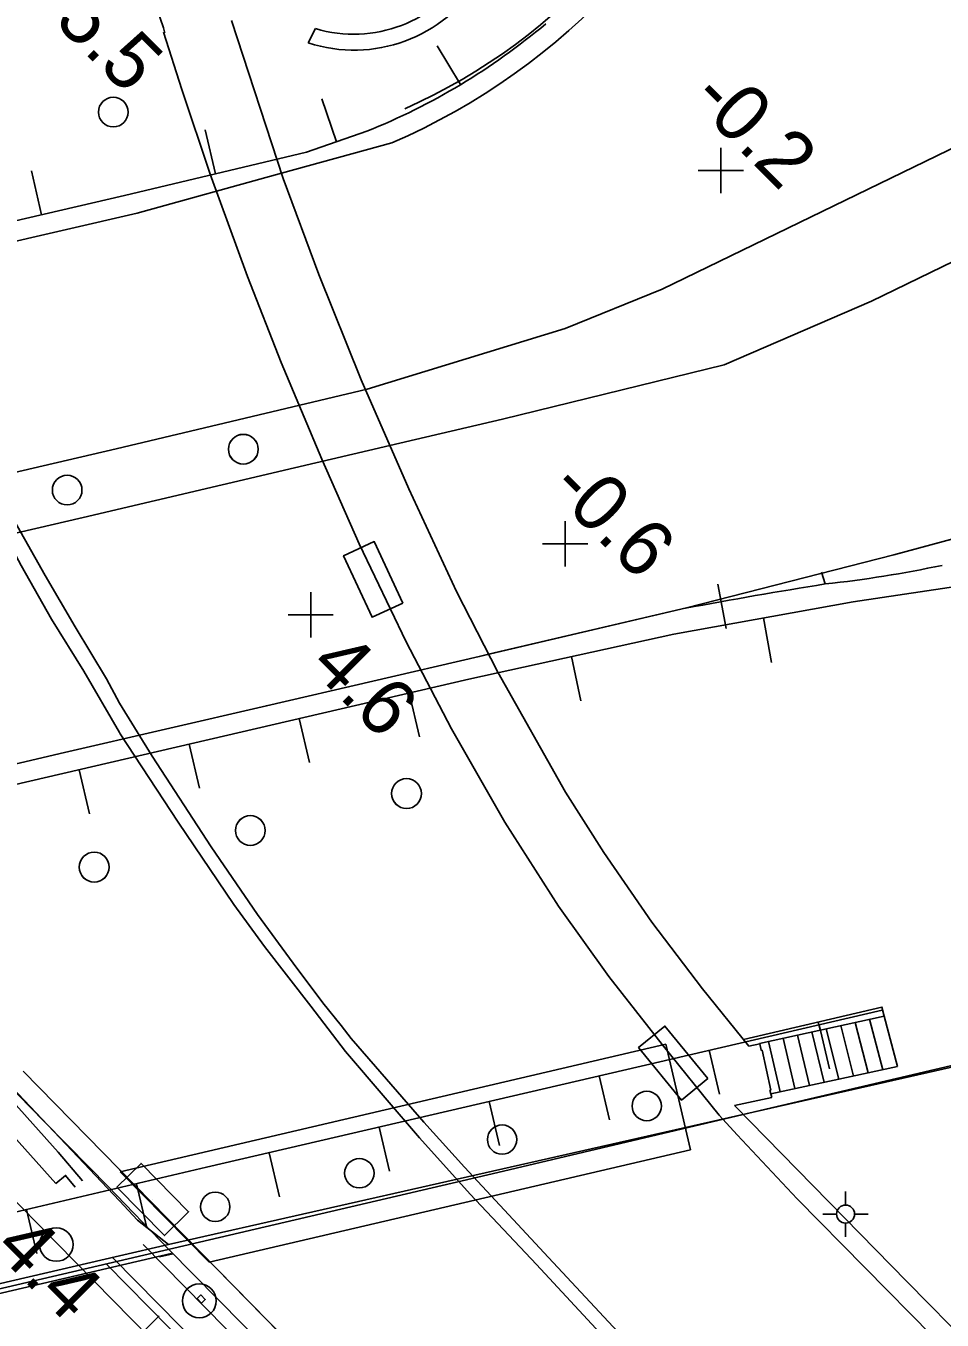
# Model space of a CAD drawing. Extents: x 1596643 to 1597288, y 13057194 to 13057957.
# Drawn here: x 1596964.2 to 1597004.8, y 13057405.5 to 13057462.8 of the extents above; entities that cross this region are included whole.
import ezdxf

# ---------------------------------------------------------------- set-up
doc = ezdxf.new("R2010")
doc.units = 0
for name, color, linetype in [('A spårmitt L', 7, 'Continuous'), ('B kabelränna större än 500 mm NK L', 7, 'Continuous'), ('BAS belysningsstolpe P', 7, 'Continuous'), ('BAS bro kantbalk ej def L', 7, 'Continuous'), ('BAS bropelare stöd ej def L', 7, 'Continuous'), ('BAS dagvatten brunn P', 7, 'Continuous'), ('BAS fastighetsgräns samfällighet L', 7, 'Continuous'), ('BAS grind bom låst L', 7, 'Continuous'), ('BAS jvg-bro kantbalk L', 7, 'Continuous'), ('BAS jvg-bro landfäste vinge L', 7, 'Continuous'), ('BAS kajkant L', 7, 'Continuous'), ('BAS Level 16', 7, 'Continuous'), ('BAS Level 18', 7, 'Continuous'), ('BAS Level 19', 7, 'Continuous'), ('BAS Level 37', 7, 'Continuous'), ('BAS markytetext T', 7, 'Continuous'), ('BAS stödmur krön L', 7, 'Continuous'), ('BAS trappa L', 7, 'Continuous'), ('BAS väg-bro pelare stöd L', 7, 'Continuous'), ('BAS vägbanekant L', 7, 'Continuous'), ('BAS vägbanekant skymd L', 7, 'Continuous'), ('E ktl sträva stag fundament L', 7, 'Continuous'), ('E ktlstolpe normal centrum P', 7, 'Continuous')]:
    doc.layers.add(name, color=color, linetype=linetype)

msp = doc.modelspace()

# ---------------------------------------------------------------- linework, layer by layer
at = {"layer": 'A spårmitt L'}
msp.add_line((1596970.138, 13057405.733), (1596968.711, 13057404.331), dxfattribs=at)
msp.add_line((1596970.138, 13057405.733), (1596968.711, 13057404.331), dxfattribs=at)
msp.add_lwpolyline([(1596887.988, 13057492.75), (1596889.66, 13057490.516), (1596900.094, 13057476.776), (1596906.53, 13057469.464), (1596928.328, 13057446.663), (1596936.899, 13057437.942), (1596957.336, 13057417.351), (1597001.928, 13057371.989), (1597034.879, 13057338.506), (1597063.764, 13057309.15)], dxfattribs=at)
at = {"layer": 'B kabelränna större än 500 mm NK L'}
for points in [[(1596966.736, 13057411.707), (1596965.667, 13057412.984), (1596959.924, 13057419.384), (1596956.53, 13057423.046), (1596952.713, 13057427.821), (1596945.579, 13057437.659), (1596942.975, 13057441.442), (1596940.764, 13057445.894), (1596936.73, 13057453.881), (1596935.025, 13057457.474)], [(1596936.26, 13057452.588), (1596938.339, 13057448.441), (1596939.871, 13057445.444), (1596942.111, 13057440.933), (1596944.761, 13057437.083), (1596949.235, 13057430.863), (1596951.919, 13057427.212), (1596955.772, 13057422.393), (1596959.185, 13057418.71), (1596965.564, 13057411.602)], [(1596965.564, 13057411.602), (1596965.986, 13057411.95), (1596966.417, 13057411.434)]]:
    msp.add_lwpolyline(points, dxfattribs=at)
at = {"layer": 'BAS belysningsstolpe P'}
for p, q in [((1597000.519, 13057411.242), (1597000.519, 13057410.642)), ((1597000.519, 13057411.242), (1597000.519, 13057410.642)), ((1596999.519, 13057410.242), (1597000.119, 13057410.242)), ((1596999.519, 13057410.242), (1597000.119, 13057410.242)), ((1597000.519, 13057409.242), (1597000.519, 13057409.844)), ((1597000.519, 13057409.242), (1597000.519, 13057409.844)), ((1597000.918, 13057410.242), (1597001.519, 13057410.242)), ((1597000.918, 13057410.242), (1597001.519, 13057410.242))]:
    msp.add_line(p, q, dxfattribs=at)
msp.add_circle((1597000.519, 13057410.242), 0.4, dxfattribs=at)
msp.add_circle((1597000.519, 13057410.242), 0.4, dxfattribs=at)
at = {"layer": 'BAS bro kantbalk ej def L'}
for p, q in [((1596969.424, 13057408.898), (1596981.122, 13057397.026)), ((1596979.817, 13057395.82), (1596967.801, 13057408.027)), ((1596968.086, 13057408.307), (1596980.102, 13057396.1))]:
    msp.add_line(p, q, dxfattribs=at)
at = {"layer": 'BAS bropelare stöd ej def L'}
msp.add_line((1596970.143, 13057408.347), (1596970.74, 13057408.488), dxfattribs=at)
for centre, radius in [((1596968.101, 13057459.002), 0.656), ((1596968.101, 13057459.002), 0.655), ((1596973.858, 13057444.084), 0.659), ((1596973.858, 13057444.084), 0.658), ((1596966.059, 13057442.277), 0.656), ((1596966.059, 13057442.277), 0.656), ((1596981.084, 13057428.848), 0.661), ((1596981.085, 13057428.848), 0.661), ((1596974.168, 13057427.214), 0.658), ((1596974.168, 13057427.214), 0.657), ((1596967.256, 13057425.595), 0.662), ((1596967.256, 13057425.595), 0.661), ((1596965.579, 13057408.891), 0.74), ((1596965.579, 13057408.891), 0.74)]:
    msp.add_circle(centre, radius, dxfattribs=at)
at = {"layer": 'BAS dagvatten brunn P'}
for p, q in [((1596979.606, 13057438.324), (1596979.606, 13057438.324)), ((1596979.606, 13057438.324), (1596979.606, 13057438.324)), ((1596992.888, 13057416.922), (1596992.888, 13057416.922)), ((1596992.888, 13057416.922), (1596992.888, 13057416.922)), ((1596969.851, 13057410.886), (1596969.851, 13057410.886)), ((1596969.851, 13057410.886), (1596969.851, 13057410.886))]:
    msp.add_line(p, q, dxfattribs=at)
for points in [[(1596980.919, 13057437.28), (1596979.653, 13057440), (1596978.293, 13057439.368), (1596979.559, 13057436.648)], [(1596980.919, 13057437.28), (1596979.653, 13057440), (1596978.293, 13057439.368), (1596979.559, 13057436.648)], [(1596994.418, 13057416.234), (1596992.521, 13057418.558), (1596991.358, 13057417.61), (1596993.255, 13057415.286)], [(1596994.418, 13057416.234), (1596992.521, 13057418.558), (1596991.358, 13057417.61), (1596993.255, 13057415.286)], [(1596968.264, 13057411.429), (1596970.369, 13057409.291), (1596971.438, 13057410.343), (1596969.333, 13057412.481)], [(1596968.264, 13057411.429), (1596970.369, 13057409.291), (1596971.438, 13057410.343), (1596969.333, 13057412.481)]]:
    msp.add_lwpolyline(points, close=True, dxfattribs=at)
at = {"layer": 'BAS fastighetsgräns samfällighet L'}
msp.add_lwpolyline([(1596970.552, 13057408.892), (1596996.104, 13057414.676), (1597030.011, 13057422.359), (1597039.004, 13057424.195), (1597047.313, 13057425.623), (1597054.119, 13057426.627), (1597059.625, 13057427.309), (1597063.942, 13057427.598), (1597069.294, 13057427.659), (1597073.697, 13057427.461), (1597077.137, 13057427.115), (1597082.905, 13057426.138), (1597086.496, 13057425.287)], dxfattribs=at)
at = {"layer": 'BAS grind bom låst L'}
for points in [[(1596977.048, 13057462.695), (1596976.732, 13057462.065)], [(1597002.222, 13057419), (1597002.128, 13057419.403), (1596996.002, 13057417.967)], [(1596999.402, 13057418.381), (1596999.314, 13057418.743)]]:
    msp.add_lwpolyline(points, dxfattribs=at)
for centre, radius, start, end in [((1596978.759, 13057468.28), 6.538, 251.9364, 44.8265), ((1596978.746, 13057468.348), 5.903, 253.2812, 43.9087)]:
    msp.add_arc(centre, radius, start, end, dxfattribs=at)
at = {"layer": 'BAS jvg-bro kantbalk L'}
for p, q in [((1596973.328, 13057463.049), (1596975.623, 13057456.069)), ((1596975.623, 13057456.069), (1596977.202, 13057451.817)), ((1596977.202, 13057451.817), (1596979.076, 13057447.148)), ((1596979.076, 13057447.148), (1596981.178, 13057442.327)), ((1596981.178, 13057442.327), (1596983.292, 13057437.784)), ((1596983.292, 13057437.784), (1596985.123, 13057434.219)), ((1596985.123, 13057434.219), (1596988.115, 13057428.91)), ((1596988.115, 13057428.91), (1596989.825, 13057426.236)), ((1596989.825, 13057426.236), (1596991.941, 13057423.155)), ((1596991.941, 13057423.155), (1596994.179, 13057420.202)), ((1596994.179, 13057420.202), (1596996.24, 13057417.676)), ((1596996.24, 13057417.676), (1596996.718, 13057417.771)), ((1596996.718, 13057417.771), (1596996.778, 13057417.494)), ((1596996.778, 13057417.494), (1596996.772, 13057417.491)), ((1596996.772, 13057417.491), (1596996.821, 13057417.489)), ((1596996.821, 13057417.489), (1596997.205, 13057415.727)), ((1596963.35, 13057416.075), (1596965.019, 13057414.353)), ((1596997.205, 13057415.727), (1596997.165, 13057415.722)), ((1596997.165, 13057415.722), (1596997.262, 13057415.406)), ((1596997.262, 13057415.406), (1596995.599, 13057415.047)), ((1596995.599, 13057415.047), (1597003.245, 13057407.244)), ((1596965.019, 13057414.353), (1596967.034, 13057412.314)), ((1596967.034, 13057412.314), (1596967.86, 13057411.471)), ((1596967.86, 13057411.471), (1596970.562, 13057408.681)), ((1596970.562, 13057408.681), (1596981.271, 13057397.819)), ((1597003.245, 13057407.244), (1597020.09, 13057390.148))]:
    msp.add_line(p, q, dxfattribs=at)
at = {"layer": 'BAS jvg-bro landfäste vinge L'}
msp.add_lwpolyline([(1596958.368, 13057405.631), (1596970.663, 13057408.503)], dxfattribs=at)
at = {"layer": 'BAS kajkant L'}
for q in [(1596995.988, 13057414.649), (1596958.36, 13057405.835)]:
    msp.add_line((1596985.13, 13057412.086), q, dxfattribs=at)
for points in [[(1596995.988, 13057414.649), (1597021.448, 13057420.619), (1597026.191, 13057421.54), (1597032.609, 13057422.915), (1597038.622, 13057424.126), (1597044.909, 13057425.247), (1597050.902, 13057426.183), (1597057.179, 13057427.05)], [(1596985.13, 13057412.086), (1596995.988, 13057414.649)]]:
    msp.add_lwpolyline(points, dxfattribs=at)
at = {"layer": 'BAS Level 16'}
for p, q in [((1596994.996, 13057456.416), (1596994.996, 13057457.416)), ((1596994.996, 13057456.416), (1596994.996, 13057457.416)), ((1596994.996, 13057456.416), (1596993.996, 13057456.416)), ((1596994.996, 13057456.416), (1596993.996, 13057456.416)), ((1596994.996, 13057456.416), (1596995.996, 13057456.416)), ((1596994.996, 13057456.416), (1596994.996, 13057455.416)), ((1596994.996, 13057456.416), (1596995.996, 13057456.416)), ((1596994.996, 13057456.416), (1596994.996, 13057455.416)), ((1596988.103, 13057439.898), (1596988.103, 13057440.898)), ((1596988.103, 13057439.898), (1596988.103, 13057440.898)), ((1596988.103, 13057439.898), (1596987.103, 13057439.898)), ((1596988.103, 13057439.898), (1596987.103, 13057439.898)), ((1596988.103, 13057439.898), (1596989.103, 13057439.898)), ((1596988.103, 13057439.898), (1596988.103, 13057438.898)), ((1596988.103, 13057439.898), (1596989.103, 13057439.898)), ((1596988.103, 13057439.898), (1596988.103, 13057438.898)), ((1596976.842, 13057436.761), (1596976.842, 13057437.761)), ((1596976.842, 13057436.761), (1596976.842, 13057437.761)), ((1596976.842, 13057436.761), (1596975.842, 13057436.761)), ((1596976.842, 13057436.761), (1596975.842, 13057436.761)), ((1596976.842, 13057436.761), (1596977.842, 13057436.761)), ((1596976.842, 13057436.761), (1596976.842, 13057435.761)), ((1596976.842, 13057436.761), (1596977.842, 13057436.761)), ((1596976.842, 13057436.761), (1596976.842, 13057435.761))]:
    msp.add_line(p, q, dxfattribs=at)
at = {"layer": 'BAS Level 18'}
for p, q in [((1596983.474, 13057460.216), (1596982.445, 13057461.931)), ((1596983.474, 13057460.216), (1596982.445, 13057461.931)), ((1596977.99, 13057457.692), (1596977.336, 13057459.582)), ((1596977.99, 13057457.692), (1596977.336, 13057459.582)), ((1596972.63, 13057456.271), (1596972.167, 13057458.217)), ((1596972.63, 13057456.271), (1596972.167, 13057458.217)), ((1596964.927, 13057454.46), (1596964.475, 13057456.408)), ((1596964.927, 13057454.46), (1596964.475, 13057456.408)), ((1596994.865, 13057438.109), (1596995.241, 13057436.145)), ((1596994.865, 13057438.109), (1596995.241, 13057436.145)), ((1596996.892, 13057436.619), (1596997.248, 13057434.651)), ((1596996.892, 13057436.619), (1596997.248, 13057434.651)), ((1596988.38, 13057434.908), (1596988.807, 13057432.954)), ((1596988.38, 13057434.908), (1596988.807, 13057432.954)), ((1596981.2, 13057433.301), (1596981.653, 13057431.353)), ((1596981.2, 13057433.301), (1596981.653, 13057431.353)), ((1596976.33, 13057432.168), (1596976.783, 13057430.22)), ((1596976.33, 13057432.168), (1596976.783, 13057430.22)), ((1596971.46, 13057431.035), (1596971.913, 13057429.087)), ((1596971.46, 13057431.035), (1596971.913, 13057429.087)), ((1596966.59, 13057429.903), (1596967.043, 13057427.955)), ((1596966.59, 13057429.903), (1596967.043, 13057427.955)), ((1596999.357, 13057418.622), (1596999.81, 13057416.674)), ((1596999.357, 13057418.622), (1596999.81, 13057416.674)), ((1596994.487, 13057417.489), (1596994.94, 13057415.541)), ((1596994.487, 13057417.489), (1596994.94, 13057415.541)), ((1596989.618, 13057416.356), (1596990.071, 13057414.408)), ((1596989.618, 13057416.356), (1596990.071, 13057414.408)), ((1596984.748, 13057415.223), (1596985.201, 13057413.275)), ((1596984.748, 13057415.223), (1596985.201, 13057413.275)), ((1596979.878, 13057414.09), (1596980.331, 13057412.142)), ((1596979.878, 13057414.09), (1596980.331, 13057412.142)), ((1596975.008, 13057412.957), (1596975.461, 13057411.009)), ((1596975.008, 13057412.957), (1596975.461, 13057411.009)), ((1596969.133, 13057411.587), (1596969.588, 13057409.639)), ((1596969.133, 13057411.587), (1596969.588, 13057409.639)), ((1596964.264, 13057410.45), (1596964.719, 13057408.502)), ((1596964.264, 13057410.45), (1596964.719, 13057408.502))]:
    msp.add_line(p, q, dxfattribs=at)
at = {"layer": 'BAS Level 19'}
msp.add_arc((1596970.417, 13057483.011), 26.104, 293.9246, 343.4998, dxfattribs=at)
at = {"layer": 'BAS Level 37'}
for points in [[(1596934.679, 13057459.15), (1596942.51, 13057442.931), (1596946.333, 13057437.601), (1596952.505, 13057428.568), (1596955.404, 13057424.94), (1596958.328, 13057421.412), (1596968.373, 13057410.821)], [(1596968.373, 13057410.821), (1596969.176, 13057409.975), (1596970.551, 13057408.898)], [(1596968.373, 13057408.389), (1596970.552, 13057408.892)], [(1596957.002, 13057405.761), (1596968.373, 13057408.389)]]:
    msp.add_lwpolyline(points, dxfattribs=at)
at = {"layer": 'BAS stödmur krön L'}
for p, q in [((1596979.323, 13057458.153), (1596976.657, 13057457.23)), ((1596976.657, 13057457.23), (1596968.602, 13057455.312)), ((1596968.602, 13057455.312), (1596936.897, 13057447.961)), ((1597000.86, 13057437.336), (1597014.477, 13057439.354)), ((1596992.924, 13057435.901), (1597000.86, 13057437.336)), ((1596983.836, 13057433.914), (1596992.924, 13057435.901)), ((1596954.214, 13057427.024), (1596983.836, 13057433.914)), ((1596972.232, 13057412.311), (1597002.133, 13057419.268)), ((1596946.558, 13057406.316), (1596972.232, 13057412.311))]:
    msp.add_line(p, q, dxfattribs=at)
msp.add_arc((1596968.45, 13057485.242), 29.19, 291.8679, 310.083, dxfattribs=at)
at = {"layer": 'BAS trappa L'}
for points in [[(1597002.222, 13057419), (1596996.714, 13057417.792)], [(1597001.583, 13057418.86), (1597002.167, 13057416.626)], [(1597002.815, 13057416.765), (1597002.222, 13057419)], [(1596999.028, 13057418.3), (1596999.575, 13057416.07)], [(1596999.667, 13057418.44), (1597000.223, 13057416.209)], [(1597000.305, 13057418.58), (1597000.871, 13057416.348)], [(1597000.944, 13057418.72), (1597001.519, 13057416.487)], [(1596997.111, 13057417.879), (1596997.631, 13057415.653)], [(1596997.75, 13057418.02), (1596998.279, 13057415.792)], [(1596998.389, 13057418.16), (1596998.927, 13057415.931)], [(1596997.214, 13057415.563), (1597002.815, 13057416.765)]]:
    msp.add_lwpolyline(points, dxfattribs=at)
at = {"layer": 'BAS väg-bro pelare stöd L'}
for p, q in [((1596968.41, 13057412.116), (1596992.562, 13057417.765)), ((1596993.65, 13057413.09), (1596992.562, 13057417.765)), ((1596972.343, 13057408.107), (1596993.65, 13057413.09)), ((1596968.41, 13057412.116), (1596972.343, 13057408.107))]:
    msp.add_line(p, q, dxfattribs=at)
for points in [[(1596968.41, 13057412.116), (1596992.562, 13057417.765)], [(1596993.65, 13057413.09), (1596992.562, 13057417.765)], [(1596972.343, 13057408.107), (1596993.65, 13057413.09)], [(1596968.41, 13057412.116), (1596972.343, 13057408.107)]]:
    msp.add_lwpolyline(points, dxfattribs=at)
for centre in [(1596991.719, 13057415.023), (1596991.719, 13057415.023), (1596985.315, 13057413.539), (1596985.315, 13057413.539), (1596978.993, 13057412.05), (1596978.993, 13057412.05), (1596972.615, 13057410.563), (1596972.615, 13057410.563)]:
    msp.add_circle(centre, 0.65, dxfattribs=at)
at = {"layer": 'BAS vägbanekant L'}
for p, q in [((1596971.137, 13057459.995), (1596970.33, 13057462.537)), ((1596972.394, 13057456.249), (1596971.137, 13057459.995)), ((1596974.037, 13057451.723), (1596972.394, 13057456.249)), ((1596975.54, 13057447.924), (1596974.037, 13057451.723)), ((1596992.403, 13057451.165), (1596988.112, 13057449.423)), ((1597001.672, 13057450.631), (1596995.144, 13057447.825)), ((1596988.112, 13057449.423), (1596979.346, 13057446.739)), ((1596977.329, 13057443.65), (1596975.54, 13057447.924)), ((1596995.144, 13057447.825), (1596985.328, 13057445.419)), ((1596978.981, 13057439.897), (1596977.329, 13057443.65)), ((1597011.782, 13057441.876), (1597002.658, 13057439.41)), ((1596981.06, 13057435.56), (1596978.981, 13057439.897)), ((1597002.658, 13057439.41), (1596993.484, 13057437.073)), ((1596993.484, 13057437.073), (1596984.304, 13057434.913)), ((1596983.074, 13057431.71), (1596981.06, 13057435.56)), ((1596985.433, 13057427.59), (1596983.074, 13057431.71)), ((1596987.814, 13057423.862), (1596985.433, 13057427.59)), ((1596990.035, 13057420.748), (1596987.814, 13057423.862)), ((1596992.397, 13057417.744), (1596990.035, 13057420.748)), ((1596994.92, 13057414.614), (1596992.397, 13057417.744)), ((1596970.491, 13057410.065), (1596964.117, 13057416.561)), ((1596995.714, 13057413.753), (1596994.92, 13057414.614)), ((1596998.375, 13057410.918), (1596995.714, 13057413.753)), ((1597004.366, 13057404.842), (1596998.375, 13057410.918)), ((1596977.952, 13057402.455), (1596970.491, 13057410.065))]:
    msp.add_line(p, q, dxfattribs=at)
for points in [[(1596971.137, 13057459.995), (1596970.33, 13057462.537)], [(1596972.394, 13057456.249), (1596971.137, 13057459.995)], [(1596954.512, 13057459.15), (1596955.118, 13057457.72), (1596955.995, 13057455.532), (1596957.034, 13057453.131), (1596958.315, 13057450.221), (1596959.9, 13057446.974), (1596961.223, 13057444.348), (1596962.637, 13057441.519), (1596964.021, 13057438.944), (1596965.364, 13057436.562), (1596966.8, 13057434.271), (1596968.373, 13057431.554)], [(1596955.457, 13057459.15), (1596956.002, 13057457.758), (1596956.837, 13057455.316), (1596957.796, 13057453.108), (1596959.138, 13057450.198), (1596960.562, 13057447.257), (1596962.227, 13057443.827), (1596963.712, 13057440.926), (1596965.086, 13057438.494), (1596966.41, 13057436.223), (1596967.803, 13057433.92)], [(1596980.43, 13057457.636), (1596975.549, 13057456.294)], [(1597005.566, 13057457.556), (1596992.403, 13057451.165)], [(1597001.669, 13057450.637), (1597007.924, 13057453.669), (1597009.458, 13057454.373), (1597011.987, 13057455.343), (1597016.883, 13057457.202), (1597016.895, 13057457.206)], [(1596974.037, 13057451.723), (1596972.394, 13057456.249)], [(1596975.54, 13057447.924), (1596974.037, 13057451.723)], [(1596992.403, 13057451.165), (1596988.112, 13057449.423)], [(1597001.672, 13057450.631), (1596995.144, 13057447.825)], [(1596988.112, 13057449.423), (1596979.346, 13057446.739)], [(1596977.329, 13057443.65), (1596975.54, 13057447.924)], [(1596995.144, 13057447.825), (1596985.328, 13057445.419)], [(1596985.328, 13057445.419), (1596980.34, 13057444.249)], [(1596978.981, 13057439.897), (1596977.329, 13057443.65)], [(1597011.782, 13057441.876), (1597002.658, 13057439.41)], [(1596981.06, 13057435.56), (1596978.981, 13057439.897)], [(1597002.658, 13057439.41), (1596993.484, 13057437.073)], [(1596999.46, 13057438.642), (1596999.623, 13057438.123)], [(1596993.484, 13057437.073), (1596984.717, 13057435.01)], [(1596983.074, 13057431.71), (1596981.06, 13057435.56)], [(1596967.803, 13057433.92), (1596968.373, 13057432.851)], [(1597133.452, 13057259.15), (1597054.729, 13057339.299), (1596995.848, 13057399.372), (1596990.433, 13057405.034), (1596987.369, 13057408.321), (1596983.644, 13057412.319), (1596981.852, 13057414.308), (1596980.193, 13057416.206), (1596978.635, 13057418.012), (1596978.187, 13057418.58), (1596977.383, 13057419.585), (1596976.059, 13057421.351), (1596974.481, 13057423.493), (1596972.433, 13057426.487), (1596969.826, 13057430.508), (1596968.373, 13057432.851)], [(1596968.373, 13057431.554), (1596968.412, 13057431.491), (1596970.968, 13057427.583), (1596973.443, 13057423.938), (1596974.798, 13057422.081), (1596976.844, 13057419.442), (1596978.382, 13057417.442), (1596980.143, 13057415.392), (1596981.65, 13057413.616), (1596983.899, 13057411.12), (1596986.841, 13057408.015), (1596993.05, 13057401.308), (1597001.071, 13057393.121), (1597017.407, 13057376.512), (1597028.562, 13057365.159), (1597039.891, 13057353.552), (1597050.384, 13057342.909), (1597065.285, 13057327.589), (1597082.629, 13057309.925), (1597099.189, 13057293.124), (1597132.621, 13057259.15)], [(1596985.433, 13057427.59), (1596983.074, 13057431.71)], [(1596987.814, 13057423.862), (1596985.433, 13057427.59)], [(1596990.035, 13057420.748), (1596987.814, 13057423.862)], [(1596992.397, 13057417.744), (1596990.035, 13057420.748)], [(1596994.92, 13057414.614), (1596992.397, 13057417.744)], [(1596970.491, 13057410.065), (1596964.117, 13057416.561)], [(1596995.714, 13057413.753), (1596994.92, 13057414.614)], [(1596998.375, 13057410.918), (1596995.714, 13057413.753)], [(1596968.93, 13057411.636), (1596968.373, 13057412.197)], [(1597004.366, 13057404.842), (1596998.375, 13057410.918)], [(1596977.952, 13057402.455), (1596970.491, 13057410.065)]]:
    msp.add_lwpolyline(points, dxfattribs=at)
for centre, radius, start, end in [((1596968.581, 13057484.991), 29.812, 293.4203, 341.0999), ((1597035.687, 13057484.383), 68.864, 192.17902, 198.33181), ((1597109.52, 13057504.501), 145.336, 196.70544, 196.79596), ((1596993.96, 13057490.406), 52.588, 276.1819, 281.8901), ((1597035.925, 13057211.038), 229.968, 99.0825, 100.64802)]:
    msp.add_arc(centre, radius, start, end, dxfattribs=at)
at = {"layer": 'BAS vägbanekant skymd L'}
for points in [[(1596975.549, 13057456.294), (1596969.153, 13057454.536), (1596962.688, 13057453.046), (1596957.894, 13057451.93), (1596953.113, 13057450.794), (1596943.549, 13057448.559), (1596937.074, 13057447.044), (1596934.001, 13057446.332), (1596924.437, 13057444.133), (1596915.451, 13057442.034), (1596910.392, 13057440.886), (1596910.146, 13057440.853), (1596910.392, 13057440.886)], [(1596979.346, 13057446.739), (1596968.227, 13057444.103), (1596961.305, 13057442.487), (1596952.401, 13057440.381), (1596943.603, 13057438.303), (1596934.215, 13057436.081), (1596926.33, 13057434.208), (1596921.412, 13057433.046), (1596921.21, 13057432.997), (1596921.412, 13057433.046)], [(1596980.34, 13057444.249), (1596976.126, 13057443.26), (1596966.766, 13057441.06), (1596957.541, 13057438.93), (1596947.883, 13057436.681), (1596938.321, 13057434.458), (1596928.922, 13057432.26), (1596924.04, 13057431.112), (1596923.794, 13057431.055), (1596924.04, 13057431.112)], [(1596984.304, 13057434.913), (1596984.717, 13057435.01), (1596984.304, 13057434.913), (1596974.878, 13057432.731), (1596965.947, 13057430.663), (1596956.687, 13057428.501), (1596947.492, 13057426.391), (1596938.505, 13057424.291), (1596934.025, 13057423.264), (1596933.664, 13057423.18), (1596934.025, 13057423.264)]]:
    msp.add_lwpolyline(points, dxfattribs=at)
at = {"layer": 'E ktl sträva stag fundament L'}
msp.add_lwpolyline([(1596971.811, 13057406.505), (1596972.008, 13057406.3), (1596972.174, 13057406.46), (1596971.977, 13057406.664), (1596971.811, 13057406.505)], dxfattribs=at)
at = {"layer": 'E ktlstolpe normal centrum P'}
msp.add_circle((1596971.909, 13057406.402), 0.75, dxfattribs=at)
msp.add_circle((1596971.909, 13057406.402), 0.75, dxfattribs=at)

# ---------------------------------------------------------------- texts
at = {"layer": 'BAS markytetext T'}
for s, p in [('5.5', (1596965.435, 13057462.999)), ('-0.2', (1596993.597, 13057459.528)), ('-0.6', (1596987.34, 13057442.279)), ('4.6', (1596976.724, 13057434.455)), ('4.4', (1596962.752, 13057408.662))]:
    msp.add_text(s, height=2.5, rotation=315, dxfattribs=at).set_placement(p)

doc.saveas('drawing.dxf')
